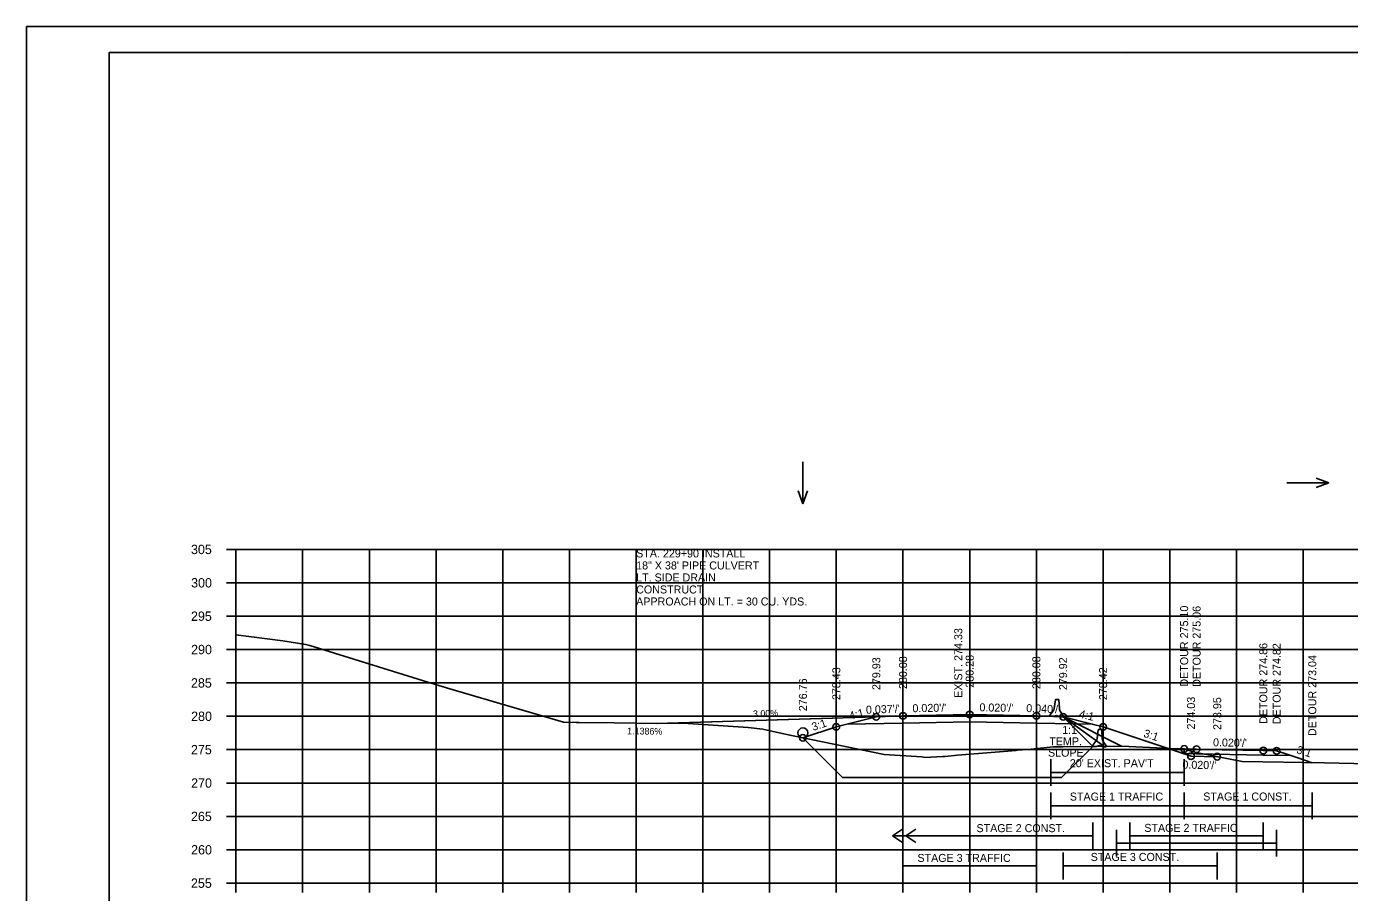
# Model space of a CAD drawing. Extents: x 4667 to 1632277, y -2100 to 724501.
# Drawn here: x 5635.8 to 5834.1, y 466.5 to 596.3 of the extents above; entities that cross this region are included whole.
import ezdxf

# ---------------------------------------------------------------- set-up
doc = ezdxf.new("R2010")
doc.units = 0
for name, color, linetype in [('R_Alt Surface', 7, 'Continuous'), ('R_Axis', 7, 'Continuous'), ('R_Axis Annot', 7, 'Continuous'), ('R_Border', 7, 'Continuous'), ('R_Border Notes', 7, 'Continuous'), ('R_Detour', 7, 'Continuous'), ('R_Detour Annot', 7, 'Continuous'), ('R_Drive', 7, 'Continuous'), ('R_Exist Surface', 7, 'Continuous'), ('R_Fin Surface', 7, 'Continuous'), ('R_Fin Surface Annot', 7, 'Continuous'), ('R_Grid', 7, 'Continuous'), ('R_MOT', 7, 'Continuous'), ('R_No Plot', 7, 'Continuous'), ('R_Proposed CofA', 7, 'Continuous'), ('R_ROW', 7, 'Continuous'), ('R_Temp Easement', 7, 'Continuous'), ('R_Water', 7, 'Continuous'), ('R_Water Annot', 7, 'Continuous'), ('T_Drafting', 7, 'Continuous')]:
    doc.layers.add(name, color=color, linetype=linetype)

msp = doc.modelspace()

# ---------------------------------------------------------------- linework, layer by layer
at = {"layer": 'R_Alt Surface'}
msp.add_lwpolyline([(5758.77, 491.76), (5767.18, 491.93), (5777.18, 492.13), (5787.18, 491.93), (5795.55, 491.77)], dxfattribs=at)
at = {"layer": 'R_Axis'}
for p, q in [((5665.78, 517.94), (5667.18, 517.94)), ((5667.18, 467.94), (5667.18, 517.94)), ((5665.78, 512.94), (5667.18, 512.94)), ((5665.78, 507.94), (5667.18, 507.94)), ((5665.78, 502.94), (5667.18, 502.94)), ((5665.78, 497.94), (5667.18, 497.94)), ((5665.78, 492.94), (5667.18, 492.94)), ((5665.78, 487.94), (5667.18, 487.94)), ((5665.78, 482.94), (5667.18, 482.94)), ((5665.78, 477.94), (5667.18, 477.94)), ((5665.78, 472.94), (5667.18, 472.94)), ((5665.78, 467.94), (5667.18, 467.94)), ((5667.18, 467.94), (5947.18, 467.94)), ((5667.18, 466.54), (5667.18, 467.94)), ((5677.18, 466.54), (5677.18, 467.94)), ((5687.18, 466.54), (5687.18, 467.94)), ((5697.18, 466.54), (5697.18, 467.94)), ((5707.18, 466.54), (5707.18, 467.94)), ((5717.18, 466.54), (5717.18, 467.94)), ((5727.18, 466.54), (5727.18, 467.94)), ((5737.18, 466.54), (5737.18, 467.94)), ((5747.18, 466.54), (5747.18, 467.94)), ((5757.18, 466.54), (5757.18, 467.94)), ((5767.18, 466.54), (5767.18, 467.94)), ((5777.18, 466.54), (5777.18, 467.94)), ((5787.18, 466.54), (5787.18, 467.94)), ((5797.18, 466.54), (5797.18, 467.94)), ((5807.18, 466.54), (5807.18, 467.94)), ((5817.18, 466.54), (5817.18, 467.94)), ((5827.18, 466.54), (5827.18, 467.94))]:
    msp.add_line(p, q, dxfattribs=at)
at = {"layer": 'R_Border'}
for p, q in [((5648.18, 592.4), (5964.36, 592.4)), ((5648.18, 386.94), (5648.18, 592.4)), ((5800.7, 592.14), (5800.7, 592.14)), ((5800.7, 592.14), (5800.7, 592.14))]:
    msp.add_line(p, q, dxfattribs=at)
at = {"layer": 'R_Detour'}
for points in [[(5825.33, 487.05), (5821.2, 487.13), (5811.2, 487.33), (5809.33, 487.37), (5809.33, 488.04)], [(5809.33, 488.04), (5810.28, 488.02), (5811.2, 488), (5815.01, 487.92), (5821.2, 487.8), (5821.96, 487.79), (5823.2, 487.76), (5824.42, 487.36), (5826.39, 486.7), (5828.54, 485.98)]]:
    msp.add_lwpolyline(points, dxfattribs=at)
at = {"layer": 'R_Drive'}
msp.add_line((5730.23, 491.88), (5763.18, 492.87), dxfattribs=at)
at = {"layer": 'R_Exist Surface'}
msp.add_lwpolyline([(5667.18, 505.15), (5674.21, 504.22), (5677.64, 503.71), (5678.27, 503.54), (5695.97, 498.06), (5699.23, 497.04), (5716.3, 492.07), (5718.2, 492.02), (5718.64, 492.02), (5723.9, 491.95), (5730.32, 491.88), (5734.21, 491.92), (5743.96, 491.28), (5746.18, 491), (5749.54, 490.24), (5764.38, 487.2), (5770, 486.86), (5770.53, 486.77), (5773.12, 486.9), (5773.52, 486.91), (5775.36, 487.12), (5784.17, 487.83), (5784.35, 487.84), (5785.92, 487.96), (5789.26, 488.33), (5789.74, 488.36), (5791.16, 488.38), (5800, 488.47), (5808.37, 488.08), (5809.33, 488.04), (5810.51, 487.66), (5810.72, 487.61), (5811.37, 487.44), (5818.03, 486.18), (5830.39, 485.95), (5848.02, 485.56)], dxfattribs=at)
at = {"layer": 'R_Fin Surface'}
msp.add_lwpolyline([(5752.18, 489.7), (5757.18, 491.37), (5758.77, 491.76), (5763.18, 492.87), (5767.18, 493.02), (5777.18, 493.22), (5787.18, 493.02), (5791.18, 492.86), (5795.55, 491.77), (5797.18, 491.36), (5810.36, 486.96), (5814.29, 486.89)], dxfattribs=at)
at = {"layer": 'R_Grid'}
for p, q in [((5667.18, 517.94), (5947.18, 517.94)), ((5667.18, 467.94), (5667.18, 517.94)), ((5677.18, 467.94), (5677.18, 517.94)), ((5687.18, 467.94), (5687.18, 517.94)), ((5697.18, 467.94), (5697.18, 517.94)), ((5707.18, 467.94), (5707.18, 517.94)), ((5717.18, 467.94), (5717.18, 517.94)), ((5727.18, 467.94), (5727.18, 517.94)), ((5737.18, 467.94), (5737.18, 517.94)), ((5747.18, 467.94), (5747.18, 517.94)), ((5757.18, 467.94), (5757.18, 517.94)), ((5767.18, 467.94), (5767.18, 517.94)), ((5777.18, 467.94), (5777.18, 517.94)), ((5787.18, 467.94), (5787.18, 517.94)), ((5797.18, 467.94), (5797.18, 517.94)), ((5807.18, 467.94), (5807.18, 517.94)), ((5817.18, 467.94), (5817.18, 517.94)), ((5827.18, 467.94), (5827.18, 517.94)), ((5667.18, 512.94), (5947.18, 512.94)), ((5667.18, 507.94), (5947.18, 507.94)), ((5667.18, 502.94), (5947.18, 502.94)), ((5667.18, 497.94), (5947.18, 497.94)), ((5667.18, 492.94), (5947.18, 492.94)), ((5667.18, 487.94), (5947.18, 487.94)), ((5667.18, 482.94), (5947.18, 482.94)), ((5667.18, 477.94), (5947.18, 477.94)), ((5667.18, 472.94), (5947.18, 472.94)), ((5667.18, 467.94), (5947.18, 467.94))]:
    msp.add_line(p, q, dxfattribs=at)
at = {"layer": 'R_MOT'}
for p, q in [((5789.84, 494.12), (5790.03, 495.43)), ((5790.09, 495.48), (5790.29, 495.48)), ((5790.48, 495.47), (5790.29, 495.48)), ((5790.63, 494.09), (5790.54, 495.41)), ((5789.19, 493.1), (5789.68, 493.74)), ((5789.19, 492.94), (5789.19, 493.1)), ((5789.69, 492.92), (5789.19, 492.94)), ((5790.19, 493.06), (5789.69, 492.92)), ((5790.68, 492.88), (5790.19, 493.06)), ((5791.18, 492.86), (5790.68, 492.88)), ((5791.19, 493.02), (5790.76, 493.7)), ((5791.18, 492.86), (5791.19, 493.02)), ((5796.27, 489.61), (5796.46, 490.92)), ((5796.53, 490.97), (5796.72, 490.96)), ((5796.91, 490.96), (5796.72, 490.96)), ((5797.06, 489.58), (5796.97, 490.9)), ((5795.62, 488.59), (5796.11, 489.23)), ((5795.62, 488.42), (5795.62, 488.59)), ((5796.12, 488.4), (5795.62, 488.42)), ((5796.62, 488.55), (5796.12, 488.4)), ((5797.12, 488.36), (5796.62, 488.55)), ((5797.62, 488.34), (5797.12, 488.36)), ((5797.62, 488.51), (5797.19, 489.18)), ((5797.62, 488.34), (5797.62, 488.51))]:
    msp.add_line(p, q, dxfattribs=at)
for centre, radius, start, end in [((5789.02, 494.25), 0.833, 322.7174, 351.7004), ((5790.09, 495.42), 0.0625, 87.7094, 171.7004), ((5790.48, 495.41), 0.0625, 3.7184, 87.7094), ((5791.46, 494.15), 0.833, 183.7184, 212.7014), ((5796.52, 490.91), 0.0625, 87.7094, 171.7004), ((5796.91, 490.89), 0.0625, 3.7184, 87.7094), ((5795.45, 489.73), 0.833, 322.7174, 351.7004), ((5797.89, 489.64), 0.833, 183.7184, 212.7014)]:
    msp.add_arc(centre, radius, start, end, dxfattribs=at)
at = {"layer": 'R_No Plot'}
for p, q in [((5635.78, 596.29), (5969.12, 596.29)), ((5763.18, 492.87), (5730.32, 491.88)), ((5791.18, 492.86), (5799.96, 488.47)), ((5791.18, 492.86), (5797.31, 488.44)), ((5799.2, 475.94), (5799.2, 471.94)), ((5823.2, 475.94), (5823.2, 471.94)), ((5799.2, 473.94), (5823.2, 473.94))]:
    msp.add_line(p, q, dxfattribs=at)
for points in [[(5635.78, 596.29), (5969.12, 596.29), (5969.12, 382.95), (5635.78, 382.95)], [(5882.1, 592.4), (5901.72, 592.4), (5901.72, 582.52), (5917.84, 582.52), (5941.04, 582.52), (5941.04, 558.18), (5964.36, 558.18), (5964.36, 386.94), (5648.18, 386.94), (5648.18, 592.4)]]:
    msp.add_lwpolyline(points, close=True, dxfattribs=at)
for points in [[(5730.32, 491.88), (5734.21, 491.92), (5743.96, 491.28), (5746.18, 491), (5749.54, 490.24), (5752.18, 489.7)], [(5752.18, 489.7), (5757.18, 491.37), (5758.77, 491.76), (5763.18, 492.87)], [(5730.32, 491.88), (5730.32, 491.88)]]:
    msp.add_lwpolyline(points, dxfattribs=at)
for centre in [(5763.18, 492.87), (5767.18, 493.02), (5777.18, 493.22), (5787.18, 493.02), (5791.18, 492.86), (5752.18, 489.7), (5757.18, 491.37), (5797.18, 491.36), (5809.33, 488.04), (5811.2, 488), (5821.2, 487.8), (5823.2, 487.76), (5810.36, 486.96), (5814.29, 486.89)]:
    msp.add_circle(centre, 0.5, dxfattribs=at)
at = {"layer": 'R_Proposed CofA'}
for p, q in [((5765.62, 475.01), (5767.12, 476.01)), ((5765.62, 475.01), (5767.12, 474.01)), ((5767.62, 475.01), (5769.12, 476.01)), ((5767.62, 475.01), (5769.12, 474.01))]:
    msp.add_line(p, q, dxfattribs=at)
at = {"layer": 'R_ROW'}
for p, q in [((5752.18, 489.7), (5758.11, 483.77)), ((5795.62, 488.42), (5790.96, 483.77)), ((5758.11, 483.77), (5790.96, 483.77))]:
    msp.add_line(p, q, dxfattribs=at)
at = {"layer": 'R_Temp Easement'}
for p, q in [((5789.33, 482.51), (5789.33, 486.51)), ((5809.33, 482.51), (5809.33, 486.51)), ((5789.33, 484.51), (5809.33, 484.51)), ((5789.33, 477.51), (5789.33, 481.51)), ((5809.33, 477.51), (5809.33, 481.51)), ((5828.54, 477.51), (5828.54, 481.51)), ((5789.33, 479.51), (5809.33, 479.51)), ((5828.54, 479.51), (5809.32, 479.51)), ((5795.62, 473.01), (5795.62, 477.01)), ((5801.2, 473.01), (5801.2, 477.01)), ((5821.2, 473.01), (5821.2, 477.01)), ((5795.62, 475.01), (5765.62, 475.01)), ((5821.2, 475.01), (5801.2, 475.01)), ((5767.18, 468.51), (5767.18, 472.51)), ((5787.18, 468.51), (5787.18, 472.51)), ((5791.18, 468.51), (5791.18, 472.51)), ((5814.29, 468.51), (5814.29, 472.51)), ((5787.18, 470.51), (5767.18, 470.51)), ((5791.18, 470.51), (5814.29, 470.51))]:
    msp.add_line(p, q, dxfattribs=at)
at = {"layer": 'R_Water'}
msp.add_circle((5752.18, 490.45), 0.75, dxfattribs=at)
at = {"layer": 'R_Water Annot'}
for p, q in [((5752.18, 531.08), (5752.18, 524.79)), ((5824.74, 527.94), (5831.02, 527.94)), ((5831.02, 527.94), (5829.1, 528.64)), ((5831.02, 527.94), (5829.1, 527.24)), ((5752.18, 524.79), (5751.48, 526.72)), ((5752.18, 524.79), (5752.88, 526.72))]:
    msp.add_line(p, q, dxfattribs=at)
at = {"layer": 'T_Drafting'}
msp.add_line((5791.18, 492.86), (5795.62, 488.42), dxfattribs=at)

# ---------------------------------------------------------------- texts
at = {"layer": 'R_Axis Annot'}
for s, p in [('305', (5660.44, 517.24)), ('300', (5660.46, 512.24)), ('295', (5660.44, 507.24)), ('290', (5660.46, 502.24)), ('285', (5660.44, 497.24)), ('280', (5660.46, 492.24)), ('275', (5660.44, 487.24)), ('270', (5660.46, 482.24)), ('265', (5660.44, 477.24)), ('260', (5660.46, 472.24)), ('255', (5660.44, 467.24))]:
    msp.add_text(s, height=1.4, dxfattribs=at).set_placement(p)
at = {"layer": 'R_Border Notes'}
for s, p in [('1:1', (5791.05, 490.29)), ('SLOPE', (5788.92, 486.89)), ('TEMP.', (5789.11, 488.59))]:
    msp.add_text(s, height=1.2, dxfattribs=at).set_placement(p)
at = {"layer": 'R_Detour Annot'}
for s, rotation, p in [('DETOUR 273.04', 90, (5829.14, 489.98)), ("0.020'/'", 358.8542, (5813.65, 488.45)), ('3:1', 342.6833, (5826.08, 487.43))]:
    msp.add_text(s, height=1.2, rotation=rotation, dxfattribs=at).set_placement(p)
at = {"layer": 'R_Drive'}
msp.add_text('3.00%', height=1, rotation=1.7352, dxfattribs=at).set_placement((5744.7, 492.81))
at = {"layer": 'R_Fin Surface Annot'}
for s, rotation, p in [('DETOUR 275.10', 90, (5809.93, 497.39)), ('DETOUR 275.06', 90, (5811.8, 497.35)), ('DETOUR 274.86', 90, (5821.8, 491.8)), ('DETOUR 274.82', 90, (5823.8, 491.76)), ('280.08', 90, (5767.78, 497.02)), ('280.28', 90, (5777.78, 497.22)), ('280.08', 90, (5787.78, 497.02)), ('278.43', 90, (5757.78, 495.37)), ('279.93', 90, (5763.78, 496.87)), ('279.92', 90, (5791.78, 496.86)), ('278.42', 90, (5797.78, 495.36)), ('276.76', 90, (5752.78, 493.7)), ('4:1', 14.0362, (5759.26, 492.4)), ("0.037'/'", 2.1356, (5761.65, 493.31)), ("0.020'/'", 1.1458, (5768.61, 493.54)), ("0.020'/'", 358.8542, (5778.63, 493.69)), ("0.040'/'", 357.7094, (5785.64, 493.58)), ('274.03', 90, (5810.96, 490.96)), ('273.95', 90, (5814.89, 490.89)), ('3:1', 18.4349, (5753.73, 490.74)), ('4:1', 345.9638, (5793.5, 492.79)), ('3:1', 341.5651, (5803.14, 489.9)), ("0.020'/'", 358.8542, (5809.06, 485.11))]:
    msp.add_text(s, height=1.2, rotation=rotation, dxfattribs=at).set_placement(p)
at = {"layer": 'R_No Plot'}
msp.add_text('1.1386%', height=1, rotation=359.3477, dxfattribs=at).set_placement((5725.82, 490.24))
at = {"layer": 'R_Temp Easement'}
msp.add_text('EXIST. 274.33', height=1.2, rotation=90, dxfattribs=at).set_placement((5776.07, 495.71))
for s, height, p in [("20' EXIST. PAV'T", 1.2, (5792.19, 485.31)), ('STAGE 1 TRAFFIC', 1.2, (5792.19, 480.31)), ('STAGE 1 CONST.', 1.1985, (5812.19, 480.32)), ('STAGE 2 CONST.', 1.1985, (5778.2, 475.58)), ('STAGE 2 TRAFFIC', 1.1985, (5803.36, 475.62)), ('STAGE 3 TRAFFIC', 1.1985, (5769.35, 471.12)), ('STAGE 3 CONST.', 1.1985, (5795.32, 471.27))]:
    msp.add_text(s, height=height, dxfattribs=at).set_placement(p)
at = {"layer": 'R_Water Annot'}
for s, p in [('STA. 229+90 INSTALL', (5727.18, 516.74)), ('18" X 38\' PIPE CULVERT', (5727.18, 514.94)), ('LT. SIDE DRAIN', (5727.18, 513.14)), ('CONSTRUCT ', (5727.18, 511.34)), ('APPROACH ON LT. = 30 CU. YDS.', (5727.18, 509.54))]:
    msp.add_text(s, height=1.2, dxfattribs=at).set_placement(p)

doc.saveas('drawing.dxf')
